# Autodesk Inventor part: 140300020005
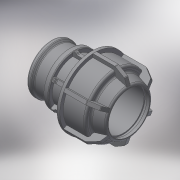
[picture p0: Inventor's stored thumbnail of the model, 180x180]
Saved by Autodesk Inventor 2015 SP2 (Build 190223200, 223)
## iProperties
Created: 2017-08
Part Number: 140300020005
Material: Generic
Description: PLASSON L.14 FEMALE ADAPTOR (SILVER) 20-1/2"
Document SubType Name: Modeling
Designer: KIM
Density: 1 g/cm^3
Appearance: Default
Author: KIM
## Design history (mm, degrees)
derived "140300.ipt"
feature "Solid1::140300.ipt"
tag "TaggingFeature1"
body "Solid1"
other parameters: "d2" = 51, "d4" = 15 deg, "d5" = 33.66, "d6" = 11.1078, "d9" = 18.631, "d10" = 42, "d11" = 24.2203, "d12" = 22.3572, "d13" = 26.0834, "d14" = 18, "d16" = 20.4, "d17" = 2.55, "d18" = 71, "d19" = 5.4, "d20" = 135 deg, "d21" = 5.4, "d22" = 22.3572, "d23" = 18, "d24" = 2.55, "d25" = 37.8, "d26" = 31.5, "d27" = 2.55, "d28" = 135 deg, "d29" = 1.53, "d31" = 1, "d44" = 0.4, "d45" = 0.6, "d46" = 150 deg, "d49" = 2.1, "d50" = 0, "d51" = 0.42, "d52" = 0.84, "d53" = 45 deg, "d55" = 6.416, "d56" = 2.1, "d57" = 0, "d58" = 0.6, "d61" = 360 deg, "G_" = 18.631, "E_" = 42, "H_" = 71, "l_" = 51, "l_2" = 18, "d54" = 16.04
